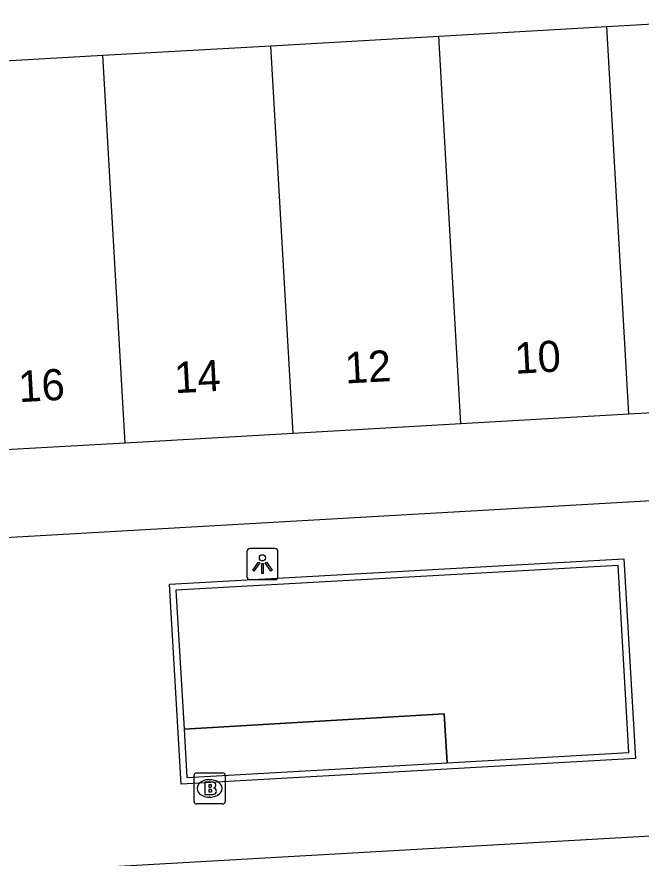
# Model space of a CAD drawing. Extents: x 155640 to 156810, y 382822 to 384046.
# Drawn here: x 156576.97 to 156597.01, y 383815.25 to 383842.24 of the extents above; entities that cross this region are included whole.
import ezdxf

# ---------------------------------------------------------------- set-up
doc = ezdxf.new("R2010")
doc.units = 0
for name, color, linetype in [('IMGEO_Brandkraan', 7, 'Continuous'), ('IMGEO_Lichtpunt', 7, 'Continuous'), ('IMGEO_Lijnafwatering', 7, 'Continuous'), ('IMGEO_Muur', 7, 'Continuous'), ('IMGEO_Pand', 7, 'Continuous'), ('IMGEO_Pand_nummerreeks', 7, 'Continuous'), ('IMGEO_Rijbaan_lokaal_gesloten', 7, 'Continuous')]:
    doc.layers.add(name, color=color, linetype=linetype)

msp = doc.modelspace()

# ---------------------------------------------------------------- linework, layer by layer
at = {"layer": 'IMGEO_Brandkraan'}
for p, q in [((156582.654, 383817.062), (156582.654, 383817.914)), ((156582.729, 383817.988), (156583.581, 383817.988)), ((156583.655, 383817.914), (156583.655, 383817.062)), ((156583.142, 383817.768), (156583.167, 383817.768)), ((156583.165, 383817.208), (156583.14, 383817.208)), ((156583.581, 383816.988), (156582.729, 383816.988))]:
    msp.add_line(p, q, dxfattribs=at)
for points in [[(156582.654, 383817.062), (156582.654, 383817.914)], [(156582.729, 383817.988), (156583.581, 383817.988)], [(156583.655, 383817.914), (156583.655, 383817.062)], [(156583.002, 383817.688), (156583.002, 383817.288), (156583.215, 383817.288)], [(156583.233, 383817.688), (156583.002, 383817.688)], [(156583.181, 383817.607), (156583.127, 383817.607), (156583.127, 383817.531)], [(156583.127, 383817.531), (156583.18, 383817.531)], [(156583.189, 383817.455), (156583.127, 383817.455), (156583.127, 383817.374)], [(156583.127, 383817.374), (156583.189, 383817.374)], [(156583.581, 383816.988), (156582.729, 383816.988)]]:
    msp.add_lwpolyline(points, dxfattribs=at)
for centre, radius, start, end in [((156582.731, 383817.912), 0.0765, 91.552, 178.448), ((156582.731, 383817.912), 0.0765, 91.552, 178.448), ((156583.579, 383817.912), 0.0765, 1.552, 88.448), ((156583.579, 383817.912), 0.0765, 1.552, 88.448), ((156583.182, 383817.569), 0.0379, 267.8285, 90.9355), ((156583.237, 383817.543), 0.145, 59.4692, 91.5367), ((156583.262, 383817.59), 0.0922, 285.5137, 58.1501), ((156583.19, 383817.414), 0.0404, 269.8759, 90.5077), ((156583.221, 383817.539), 0.251, 268.6676, 293.5347), ((156583.267, 383817.398), 0.105, 301.3115, 78.989), ((156582.731, 383817.064), 0.0765, 181.552, 268.448), ((156582.731, 383817.064), 0.0765, 181.552, 268.448), ((156583.579, 383817.064), 0.0765, 271.552, 358.448), ((156583.579, 383817.064), 0.0765, 271.552, 358.448)]:
    msp.add_arc(centre, radius, start, end, dxfattribs=at)
for centre, major_axis, ratio, start_param, end_param in [((156583.141, 383817.488), (-0.387, 0.002), 0.722429, 4.712389, 7.853982), ((156583.166, 383817.488), (-0.39, 0.002), 0.717154, 1.570796, 4.712389)]:
    msp.add_ellipse(centre, major_axis=major_axis, ratio=ratio, start_param=start_param, end_param=end_param, dxfattribs=at)
at = {"layer": 'IMGEO_Lichtpunt'}
for p, q in [((156585.254, 383825.182), (156584.446, 383825.182)), ((156585.254, 383825.182), (156584.446, 383825.182)), ((156584.352, 383825.087), (156584.352, 383824.28)), ((156584.352, 383825.087), (156584.352, 383824.28)), ((156585.348, 383824.28), (156585.348, 383825.087)), ((156585.348, 383824.28), (156585.348, 383825.087)), ((156584.446, 383824.186), (156585.254, 383824.186)), ((156584.446, 383824.186), (156585.254, 383824.186))]:
    msp.add_line(p, q, dxfattribs=at)
for points in [[(156584.726, 383824.751), (156584.765, 383824.723), (156584.577, 383824.461), (156584.539, 383824.488), (156584.726, 383824.751)], [(156584.828, 383824.703), (156584.875, 383824.703), (156584.875, 383824.381), (156584.828, 383824.381), (156584.828, 383824.703)], [(156584.938, 383824.723), (156584.976, 383824.75), (156585.163, 383824.488), (156585.124, 383824.46), (156584.938, 383824.723)]]:
    msp.add_lwpolyline(points, dxfattribs=at)
msp.add_circle((156584.851, 383824.885), 0.0994, dxfattribs=at)
for centre, start, end in [((156584.446, 383825.087), 90, 180), ((156584.446, 383825.087), 90, 180), ((156585.254, 383825.087), 0, 90), ((156585.254, 383825.087), 0, 90), ((156584.446, 383824.28), 180, 270), ((156584.446, 383824.28), 180, 270), ((156585.254, 383824.28), 270, 0), ((156585.254, 383824.28), 270, 360)]:
    msp.add_arc(centre, 0.0946, start, end, dxfattribs=at)
at = {"layer": 'IMGEO_Lijnafwatering'}
for points in [[(156598.654, 383826.785), (156572.094, 383825.268)], [(156599.18, 383816.064), (156573.301, 383814.59)]]:
    msp.add_lwpolyline(points, dxfattribs=at)
at = {"layer": 'IMGEO_Muur'}
for points in [[(156582.243, 383817.625), (156581.865, 383824.036), (156596.454, 383824.852), (156596.824, 383818.451), (156582.243, 383817.625)], [(156590.776, 383818.308), (156596.613, 383818.639), (156596.265, 383824.641), (156582.076, 383823.847), (156582.333, 383819.389)], [(156582.333, 383819.389), (156590.685, 383819.878), (156590.776, 383818.308)], [(156582.333, 383819.389), (156582.423, 383817.835), (156590.776, 383818.308)]]:
    msp.add_lwpolyline(points, dxfattribs=at)
at = {"layer": 'IMGEO_Pand'}
for points in [[(156595.902, 383841.931), (156601.293, 383842.24)], [(156590.511, 383841.622), (156595.902, 383841.931)], [(156596.615, 383829.49), (156595.902, 383841.931)], [(156585.12, 383841.313), (156590.511, 383841.622)], [(156591.224, 383829.182), (156590.511, 383841.622)], [(156579.729, 383841.005), (156585.12, 383841.313)], [(156585.833, 383828.875), (156585.12, 383841.313)], [(156574.339, 383840.696), (156579.729, 383841.005)], [(156580.442, 383828.567), (156579.729, 383841.005)], [(156602.005, 383829.798), (156596.615, 383829.49)], [(156596.615, 383829.49), (156591.224, 383829.182)], [(156591.224, 383829.182), (156585.833, 383828.875)], [(156585.833, 383828.875), (156580.442, 383828.567)], [(156580.442, 383828.567), (156575.051, 383828.259)]]:
    msp.add_lwpolyline(points, dxfattribs=at)
at = {"layer": 'IMGEO_Rijbaan_lokaal_gesloten'}
msp.add_lwpolyline([(156590.776, 383818.308), (156590.685, 383819.878), (156582.333, 383819.389)], dxfattribs=at)

# ---------------------------------------------------------------- texts
at = {"layer": 'IMGEO_Pand_nummerreeks'}
for s, p in [('10', (156592.966, 383830.787)), ('12', (156587.52, 383830.476)), ('14', (156582.045, 383830.164)), ('16', (156577.041, 383829.878))]:
    msp.add_text(s, height=1, rotation=3.0711, dxfattribs=at).set_placement(p)

doc.saveas('drawing.dxf')
